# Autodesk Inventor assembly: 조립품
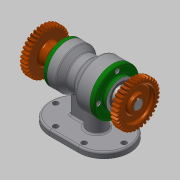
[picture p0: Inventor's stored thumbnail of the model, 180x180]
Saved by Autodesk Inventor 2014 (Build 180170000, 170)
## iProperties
Created: 2020-01
Part Number: 조립품
Document SubType Name: Assembly
Designer: kh
Author: kh
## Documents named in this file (13)
- C:\Users\kh\Desktop\700104V1034\조립품.iam
- C:\Users\kh\Desktop\700104V1034\본체.ipt
- C:\Users\kh\Desktop\700104V1034\축.ipt
- C:\Users\kh\Desktop\700104V1034\베어링 6203.ipt
- C:\Users\kh\Desktop\700104V1034\베어링 6205.ipt
- C:\Users\kh\Desktop\700104V1034\앞커버.ipt
- C:\Users\kh\Desktop\700104V1034\뒤커버.ipt
- C:\Users\kh\Desktop\700104V1034\오일 실 17 30 8.ipt
- C:\Users\kh\Desktop\700104V1034\오일 실 25 38 8.ipt
- C:\Users\kh\Desktop\700104V1034\볼트 M4.ipt
- C:\Users\kh\Desktop\700104V1034\키 5 x 5 x 18.ipt
- C:\Users\kh\Desktop\700104V1034\스퍼기어.ipt
- C:\Users\kh\Desktop\700104V1034\멈춤나사 M3.ipt
